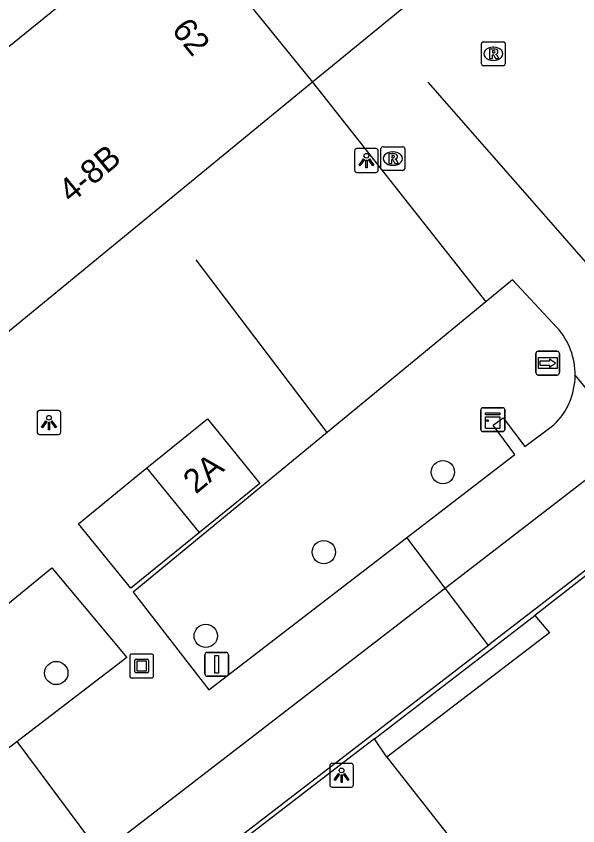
# Model space of a CAD drawing. Extents: x 161087 to 161922, y 382574 to 383873.
# Drawn here: x 161395.56 to 161419.17, y 383128.96 to 383162.97 of the extents above; entities that cross this region are included whole.
import ezdxf

# ---------------------------------------------------------------- set-up
doc = ezdxf.new("R2010")
doc.units = 0
for name, color, linetype in [('IMGEO_Boom', 7, 'Continuous'), ('IMGEO_Kast', 7, 'Continuous'), ('IMGEO_Kunstobject', 7, 'Continuous'), ('IMGEO_Lichtpunt', 7, 'Continuous'), ('IMGEO_Lijnafwatering', 7, 'Continuous'), ('IMGEO_Pand', 7, 'Continuous'), ('IMGEO_Pand_nummerreeks', 7, 'Continuous'), ('IMGEO_Rioolput', 7, 'Continuous'), ('IMGEO_Verkeersbordpaal', 7, 'Continuous'), ('IMGEO_Voetgangersgebied_open', 7, 'Continuous'), ('IMGEO_Voetpad_op_trap', 7, 'Continuous'), ('IMGEO_Wegwijzer', 7, 'Continuous')]:
    doc.layers.add(name, color=color, linetype=linetype)

msp = doc.modelspace()

# ---------------------------------------------------------------- linework, layer by layer
at = {"layer": 'IMGEO_Boom'}
for centre in [(161413.498, 383143.815), (161408.491, 383140.454), (161403.528, 383136.935), (161397.247, 383135.375)]:
    msp.add_circle(centre, 0.489, dxfattribs=at)
at = {"layer": 'IMGEO_Kast'}
for p, q in [((161415.169, 383146.516), (161416.01, 383146.516)), ((161416.01, 383146.516), (161415.169, 383146.516)), ((161415.094, 383145.591), (161415.094, 383146.432)), ((161415.094, 383146.432), (161415.094, 383145.591)), ((161416.094, 383146.441), (161416.094, 383145.6)), ((161416.094, 383145.6), (161416.094, 383146.441)), ((161416.019, 383145.516), (161415.178, 383145.516)), ((161415.178, 383145.516), (161416.019, 383145.516))]:
    msp.add_line(p, q, dxfattribs=at)
for points in [[(161415.289, 383146.306), (161415.889, 383146.306), (161415.889, 383146.221), (161415.289, 383146.221), (161415.289, 383146.306)], [(161415.289, 383146.131), (161415.889, 383146.131), (161415.889, 383145.642), (161415.289, 383145.642), (161415.289, 383146.131)]]:
    msp.add_lwpolyline(points, dxfattribs=at)
msp.add_circle((161415.373, 383145.98), 0.0377, dxfattribs=at)
for centre, start, end in [((161415.172, 383146.438), 92.4484, 184.2845), ((161415.172, 383146.438), 92.4484, 184.2845), ((161416.016, 383146.438), 2.4484, 94.2845), ((161416.016, 383146.438), 2.4484, 94.2845), ((161415.172, 383145.594), 182.4484, 274.2845), ((161415.172, 383145.594), 182.4484, 274.2845), ((161416.016, 383145.594), 272.4484, 4.2845), ((161416.016, 383145.594), 272.4484, 4.2845)]:
    msp.add_arc(centre, 0.0779, start, end, dxfattribs=at)
at = {"layer": 'IMGEO_Kunstobject'}
for p, q in [((161400.334, 383136.085), (161400.334, 383135.244)), ((161400.334, 383136.085), (161400.334, 383135.244)), ((161401.25, 383136.169), (161400.409, 383136.169)), ((161401.25, 383136.169), (161400.409, 383136.169)), ((161400.548, 383135.433), (161400.548, 383135.907)), ((161400.598, 383135.957), (161401.072, 383135.957)), ((161401.122, 383135.907), (161401.122, 383135.433)), ((161401.334, 383135.253), (161401.334, 383136.094)), ((161401.334, 383135.253), (161401.334, 383136.094)), ((161400.628, 383135.857), (161400.628, 383135.483)), ((161401.022, 383135.877), (161400.648, 383135.877)), ((161401.042, 383135.483), (161401.042, 383135.857)), ((161401.072, 383135.383), (161400.598, 383135.383)), ((161400.648, 383135.463), (161401.022, 383135.463)), ((161400.418, 383135.169), (161401.259, 383135.169)), ((161400.418, 383135.169), (161401.259, 383135.169))]:
    msp.add_line(p, q, dxfattribs=at)
for centre, radius, start, end in [((161400.412, 383136.091), 0.0779, 92.4484, 184.2845), ((161400.412, 383136.091), 0.0779, 92.4484, 184.2845), ((161400.598, 383135.907), 0.05, 90, 180), ((161401.072, 383135.907), 0.05, 360, 90), ((161401.256, 383136.091), 0.0779, 2.4484, 94.2845), ((161401.256, 383136.091), 0.0779, 2.4484, 94.2845), ((161400.648, 383135.857), 0.02, 90, 180), ((161401.022, 383135.857), 0.02, 360, 90), ((161400.412, 383135.247), 0.0779, 182.4484, 274.2845), ((161400.412, 383135.247), 0.0779, 182.4484, 274.2845), ((161400.598, 383135.433), 0.05, 180, 270), ((161400.648, 383135.483), 0.02, 180, 270), ((161401.022, 383135.483), 0.02, 270, 0), ((161401.072, 383135.433), 0.05, 270, 0), ((161401.256, 383135.247), 0.0779, 272.4484, 4.2845), ((161401.256, 383135.247), 0.0779, 272.4484, 4.2845)]:
    msp.add_arc(centre, radius, start, end, dxfattribs=at)
at = {"layer": 'IMGEO_Lichtpunt'}
for p, q in [((161410.686, 383157.404), (161409.878, 383157.404)), ((161410.686, 383157.404), (161409.878, 383157.404)), ((161409.784, 383157.309), (161409.784, 383156.502)), ((161409.784, 383157.309), (161409.784, 383156.502)), ((161410.78, 383156.502), (161410.78, 383157.309)), ((161410.78, 383156.502), (161410.78, 383157.309)), ((161409.878, 383156.408), (161410.686, 383156.408)), ((161409.878, 383156.408), (161410.686, 383156.408)), ((161396.44, 383146.302), (161396.44, 383145.495)), ((161396.44, 383146.302), (161396.44, 383145.495)), ((161397.342, 383146.397), (161396.534, 383146.397)), ((161397.342, 383146.397), (161396.534, 383146.397)), ((161397.436, 383145.495), (161397.436, 383146.302)), ((161397.436, 383145.495), (161397.436, 383146.302)), ((161396.534, 383145.401), (161397.342, 383145.401)), ((161396.534, 383145.401), (161397.342, 383145.401)), ((161408.739, 383131.485), (161408.739, 383130.678)), ((161408.739, 383131.485), (161408.739, 383130.678)), ((161409.641, 383131.58), (161408.833, 383131.58)), ((161409.641, 383131.58), (161408.833, 383131.58)), ((161409.735, 383130.678), (161409.735, 383131.485)), ((161409.735, 383130.678), (161409.735, 383131.485)), ((161408.833, 383130.584), (161409.641, 383130.584)), ((161408.833, 383130.584), (161409.641, 383130.584))]:
    msp.add_line(p, q, dxfattribs=at)
for points in [[(161410.158, 383156.973), (161410.197, 383156.945), (161410.009, 383156.683), (161409.971, 383156.71), (161410.158, 383156.973)], [(161410.26, 383156.925), (161410.307, 383156.925), (161410.307, 383156.603), (161410.26, 383156.603), (161410.26, 383156.925)], [(161410.37, 383156.945), (161410.408, 383156.972), (161410.595, 383156.71), (161410.556, 383156.682), (161410.37, 383156.945)], [(161396.814, 383145.966), (161396.853, 383145.938), (161396.665, 383145.676), (161396.627, 383145.703), (161396.814, 383145.966)], [(161396.916, 383145.918), (161396.963, 383145.918), (161396.963, 383145.596), (161396.916, 383145.596), (161396.916, 383145.918)], [(161397.026, 383145.938), (161397.064, 383145.965), (161397.251, 383145.703), (161397.212, 383145.675), (161397.026, 383145.938)], [(161409.113, 383131.149), (161409.152, 383131.121), (161408.964, 383130.859), (161408.926, 383130.886), (161409.113, 383131.149)], [(161409.325, 383131.121), (161409.363, 383131.148), (161409.55, 383130.886), (161409.511, 383130.858), (161409.325, 383131.121)], [(161409.215, 383131.101), (161409.262, 383131.101), (161409.262, 383130.779), (161409.215, 383130.779), (161409.215, 383131.101)]]:
    msp.add_lwpolyline(points, dxfattribs=at)
for centre in [(161410.283, 383157.107), (161396.939, 383146.1), (161409.238, 383131.283)]:
    msp.add_circle(centre, 0.0994, dxfattribs=at)
for centre, start, end in [((161409.878, 383157.309), 90, 180), ((161409.878, 383157.309), 90, 180), ((161410.686, 383157.309), 0, 90), ((161410.686, 383157.309), 0, 90), ((161409.878, 383156.502), 180, 270), ((161409.878, 383156.502), 180, 270), ((161410.686, 383156.502), 270, 0), ((161410.686, 383156.502), 270, 360), ((161396.534, 383146.302), 90, 180), ((161396.534, 383146.302), 90, 180), ((161397.342, 383146.302), 0, 90), ((161397.342, 383146.302), 0, 90), ((161396.534, 383145.495), 180, 270), ((161396.534, 383145.495), 180, 270), ((161397.342, 383145.495), 270, 0), ((161397.342, 383145.495), 270, 360), ((161408.833, 383131.485), 90, 180), ((161408.833, 383131.485), 90, 180), ((161409.641, 383131.485), 0, 90), ((161409.641, 383131.485), 0, 90), ((161408.833, 383130.678), 180, 270), ((161408.833, 383130.678), 180, 270), ((161409.641, 383130.678), 270, 0), ((161409.641, 383130.678), 270, 360)]:
    msp.add_arc(centre, 0.0946, start, end, dxfattribs=at)
at = {"layer": 'IMGEO_Lijnafwatering'}
for points in [[(161424.281, 383147.183), (161412.881, 383160.192)], [(161408.63, 383145.48), (161403.13, 383152.734)], [(161415.411, 383136.537), (161413.586, 383138.945), (161411.981, 383141.062)], [(161421.584, 383141.295), (161415.49, 383136.598)], [(161400.925, 383125.4), (161415.49, 383136.598)], [(161400.84, 383125.485), (161399.111, 383127.795), (161395.596, 383132.493)]]:
    msp.add_lwpolyline(points, dxfattribs=at)
at = {"layer": 'IMGEO_Pand'}
for points in [[(161402.217, 383167.338), (161388.426, 383156.163)], [(161402.217, 383167.338), (161402.307, 383167.227), (161408.019, 383160.194)], [(161408.019, 383160.194), (161407.863, 383160.065), (161395.023, 383149.541), (161394.505, 383149.117)], [(161401.056, 383143.989), (161403.596, 383146.055), (161405.797, 383143.342), (161403.261, 383141.284)], [(161403.261, 383141.284), (161400.377, 383138.943), (161398.177, 383141.643), (161400.835, 383143.809), (161401.056, 383143.989)], [(161403.261, 383141.284), (161401.056, 383143.989)]]:
    msp.add_lwpolyline(points, dxfattribs=at)
at = {"layer": 'IMGEO_Rioolput'}
for p, q in [((161415.117, 383160.963), (161415.117, 383161.815)), ((161415.192, 383161.889), (161416.044, 383161.889)), ((161416.118, 383161.815), (161416.118, 383160.963)), ((161415.605, 383161.669), (161415.63, 383161.669)), ((161415.628, 383161.109), (161415.603, 383161.109)), ((161416.044, 383160.889), (161415.192, 383160.889)), ((161410.893, 383156.559), (161410.893, 383157.411)), ((161410.968, 383157.485), (161411.82, 383157.485)), ((161411.894, 383157.411), (161411.894, 383156.559)), ((161411.381, 383157.265), (161411.406, 383157.265)), ((161411.404, 383156.705), (161411.379, 383156.705)), ((161411.82, 383156.485), (161410.968, 383156.485))]:
    msp.add_line(p, q, dxfattribs=at)
for points in [[(161415.117, 383160.963), (161415.117, 383161.815)], [(161415.192, 383161.889), (161416.044, 383161.889)], [(161416.118, 383161.815), (161416.118, 383160.963)], [(161415.706, 383161.587), (161415.454, 383161.589), (161415.454, 383161.189)], [(161415.632, 383161.508), (161415.578, 383161.508), (161415.578, 383161.427)], [(161415.578, 383161.427), (161415.63, 383161.427)], [(161415.454, 383161.189), (161415.578, 383161.189), (161415.578, 383161.351), (161415.589, 383161.351)], [(161415.636, 383161.322), (161415.707, 383161.189), (161415.847, 383161.189), (161415.782, 383161.315)], [(161416.044, 383160.889), (161415.192, 383160.889)], [(161410.893, 383156.559), (161410.893, 383157.411)], [(161410.968, 383157.485), (161411.82, 383157.485)], [(161411.894, 383157.411), (161411.894, 383156.559)], [(161411.482, 383157.183), (161411.23, 383157.185), (161411.23, 383156.785)], [(161411.408, 383157.104), (161411.354, 383157.104), (161411.354, 383157.023)], [(161411.354, 383157.023), (161411.406, 383157.023)], [(161411.23, 383156.785), (161411.354, 383156.785), (161411.354, 383156.947), (161411.365, 383156.947)], [(161411.412, 383156.918), (161411.483, 383156.785), (161411.623, 383156.785), (161411.558, 383156.911)], [(161411.82, 383156.485), (161410.968, 383156.485)]]:
    msp.add_lwpolyline(points, dxfattribs=at)
for centre, radius, start, end in [((161415.194, 383161.813), 0.0765, 91.552, 178.448), ((161415.194, 383161.813), 0.0765, 91.552, 178.448), ((161416.042, 383161.813), 0.0765, 1.552, 88.448), ((161416.042, 383161.813), 0.0765, 1.552, 88.448), ((161415.614, 383161.616), 0.19, 274.7715, 282.9687), ((161415.638, 383161.412), 0.0964, 77.0061, 93.1865), ((161415.652, 383161.469), 0.0378, 276.6634, 79.6772), ((161415.705, 383161.477), 0.109, 350.3612, 89.416), ((161415.703, 383161.477), 0.112, 277.5842, 350.9817), ((161415.588, 383161.298), 0.0533, 26.0293, 88.6989), ((161415.687, 383161.262), 0.108, 29.5134, 73.7905), ((161415.194, 383160.965), 0.0765, 181.552, 268.448), ((161415.194, 383160.965), 0.0765, 181.552, 268.448), ((161416.042, 383160.965), 0.0765, 271.552, 358.448), ((161416.042, 383160.965), 0.0765, 271.552, 358.448), ((161410.97, 383157.409), 0.0765, 91.552, 178.448), ((161410.97, 383157.409), 0.0765, 91.552, 178.448), ((161411.818, 383157.409), 0.0765, 1.552, 88.448), ((161411.818, 383157.409), 0.0765, 1.552, 88.448), ((161411.39, 383157.212), 0.19, 274.7715, 282.9687), ((161411.414, 383157.008), 0.0964, 77.0061, 93.1865), ((161411.428, 383157.065), 0.0378, 276.6634, 79.6772), ((161411.481, 383157.073), 0.109, 350.3612, 89.416), ((161411.479, 383157.073), 0.112, 277.5842, 350.9817), ((161411.364, 383156.894), 0.0533, 26.0293, 88.6989), ((161411.463, 383156.858), 0.108, 29.5134, 73.7905), ((161410.97, 383156.561), 0.0765, 181.552, 268.448), ((161410.97, 383156.561), 0.0765, 181.552, 268.448), ((161411.818, 383156.561), 0.0765, 271.552, 358.448), ((161411.818, 383156.561), 0.0765, 271.552, 358.448)]:
    msp.add_arc(centre, radius, start, end, dxfattribs=at)
for centre, major_axis, ratio, start_param, end_param in [((161415.604, 383161.389), (-0.387, 0.002), 0.722429, 4.712389, 7.853982), ((161415.629, 383161.389), (-0.39, 0.002), 0.717154, 1.570796, 4.712389), ((161411.38, 383156.985), (-0.387, 0.002), 0.722429, 4.712389, 7.853982), ((161411.405, 383156.985), (-0.39, 0.002), 0.717154, 1.570796, 4.712389)]:
    msp.add_ellipse(centre, major_axis=major_axis, ratio=ratio, start_param=start_param, end_param=end_param, dxfattribs=at)
at = {"layer": 'IMGEO_Verkeersbordpaal'}
for p, q in [((161403.594, 383136.239), (161404.384, 383136.239)), ((161404.384, 383136.239), (161403.594, 383136.239)), ((161403.494, 383135.339), (161403.494, 383136.139)), ((161403.494, 383136.139), (161403.494, 383135.339)), ((161404.484, 383136.139), (161404.484, 383135.339)), ((161404.484, 383135.339), (161404.484, 383136.139)), ((161404.384, 383135.239), (161403.594, 383135.239)), ((161403.594, 383135.239), (161404.384, 383135.239))]:
    msp.add_line(p, q, dxfattribs=at)
msp.add_lwpolyline([(161403.914, 383136.114), (161404.064, 383136.114), (161404.064, 383135.364), (161403.914, 383135.364), (161403.914, 383136.114)], dxfattribs=at)
for centre, start, end in [((161403.594, 383136.139), 90, 180), ((161403.594, 383136.139), 90, 180), ((161404.384, 383136.139), 0, 90), ((161404.384, 383136.139), 360, 90), ((161403.594, 383135.339), 180, 270), ((161403.594, 383135.339), 180, 270), ((161404.384, 383135.339), 270, 0), ((161404.384, 383135.339), 270, 0)]:
    msp.add_arc(centre, 0.1, start, end, dxfattribs=at)
at = {"layer": 'IMGEO_Voetgangersgebied_open'}
for points in [[(161416.831, 383167.411), (161408.019, 383160.194)], [(161408.019, 383160.194), (161415.295, 383150.962)], [(161418.293, 383149.892), (161416.429, 383151.894), (161415.295, 383150.962)], [(161415.295, 383150.962), (161400.48, 383138.776), (161403.665, 383134.667), (161416.525, 383144.556), (161415.614, 383145.787), (161416.034, 383146.099), (161416.943, 383144.888), (161418.161, 383145.796)], [(161419.056, 383147.871), (161421.439, 383144.995)], [(161362.866, 383099.876), (161421.439, 383144.995)], [(161421.74, 383141.212), (161417.357, 383137.788)], [(161397.058, 383139.799), (161400.206, 383136.021), (161387.42, 383126.235), (161384.635, 383129.62), (161397.058, 383139.799)], [(161410.626, 383132.608), (161409.678, 383131.89), (161364.77, 383097.35)], [(161411.138, 383131.841), (161413.877, 383128.367)]]:
    msp.add_lwpolyline(points, dxfattribs=at)
for centre, radius, start, end in [((161416.105, 383147.911), 2.951, 359.2143, 42.1524), ((161416.141, 383147.898), 2.916, 313.8667, 359.4698)]:
    msp.add_arc(centre, radius, start, end, dxfattribs=at)
at = {"layer": 'IMGEO_Voetpad_op_trap'}
for points in [[(161410.626, 383132.608), (161417.357, 383137.788)], [(161417.357, 383137.788), (161417.973, 383137.059), (161411.138, 383131.841)], [(161411.138, 383131.841), (161410.626, 383132.608)]]:
    msp.add_lwpolyline(points, dxfattribs=at)
at = {"layer": 'IMGEO_Wegwijzer'}
for p, q in [((161417.508, 383148.894), (161418.298, 383148.894)), ((161418.298, 383148.894), (161417.508, 383148.894)), ((161417.408, 383147.994), (161417.408, 383148.794)), ((161417.408, 383148.794), (161417.408, 383147.994)), ((161418.398, 383148.794), (161418.398, 383147.994)), ((161418.398, 383147.994), (161418.398, 383148.794)), ((161418.298, 383147.894), (161417.508, 383147.894)), ((161417.508, 383147.894), (161418.298, 383147.894))]:
    msp.add_line(p, q, dxfattribs=at)
for points in [[(161417.509, 383148.626), (161418.297, 383148.626), (161418.297, 383148.162), (161417.509, 383148.162), (161417.509, 383148.626)], [(161417.574, 383148.478), (161417.574, 383148.394), (161417.574, 383148.31), (161417.985, 383148.31), (161417.985, 383148.227), (161418.232, 383148.394), (161417.985, 383148.561), (161417.985, 383148.478), (161417.574, 383148.478)]]:
    msp.add_lwpolyline(points, dxfattribs=at)
for centre, start, end in [((161417.508, 383148.794), 90, 180), ((161417.508, 383148.794), 90, 180), ((161418.298, 383148.794), 0, 90), ((161418.298, 383148.794), 360, 90), ((161417.508, 383147.994), 180, 270), ((161417.508, 383147.994), 180, 270), ((161418.298, 383147.994), 270, 0), ((161418.298, 383147.994), 270, 0)]:
    msp.add_arc(centre, 0.1, start, end, dxfattribs=at)

# ---------------------------------------------------------------- texts
at = {"layer": 'IMGEO_Pand_nummerreeks'}
for s, rotation, p in [('62', 309.2269, (161402.061, 383162.373)), ('4-8B', 39.523, (161397.865, 383155.083)), ('2A', 39.8622, (161403.111, 383142.864))]:
    msp.add_text(s, height=1, rotation=rotation, dxfattribs=at).set_placement(p)

doc.saveas('drawing.dxf')
